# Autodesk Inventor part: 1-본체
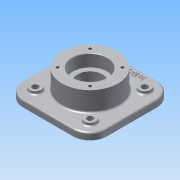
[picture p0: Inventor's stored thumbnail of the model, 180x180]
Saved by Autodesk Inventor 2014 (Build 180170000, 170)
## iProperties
Created: 2015-09
Part Number: 1-본체
Material: 알루미늄 6061
Document SubType Name: Modeling
Designer: study
Density: 2.71 g/cm^3
Appearance: 알루미늄 - 평지
Mass: 1464.66 g
Surface Area: 800.918 cm^2
Volume: 540.466 cm^3
Author: study
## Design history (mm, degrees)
sketch "스케치1"
  geometry: L1 (-45, 75)-(45, 75); L2 (75, 45)-(75, -45); L3 (45, -75)-(-45, -75); L4 (-75, -45)-(-75, 45); L5 (-75, 75)-(75, -75); L6 (75, 75)-(-75, -75); A1 r 30 centre (-45, 45) between (-45, 75) and (-75, 45); A2 r 30 centre (45, 45) between (75, 45) and (45, 75); A3 r 30 centre (45, -45) between (45, -75) and (75, -45); A4 r 30 centre (-45, -45) between (-75, -45) and (-45, -75); 1 further point
  constraints: 12 end point, 8 point on circle, 8 point on line, 8 tangent, 4 centre point, 3 equal radius, 2 midpoint, 2 parallel, 1 horizontal, 1 perpendicular
  dimensions: "d0" = 150 distance of L5.start L6.start; "d1" = 150 distance of L6.start L5.end; "d2" = 30 radius of A1
extrude "돌출1" new body sketch "스케치1" distance "d3" = 12; taper "d4" = 0 deg
node "작업 평면1"
sketch "스케치2"
  geometry: C1 r 50 at (0, 0); 1 further point
  constraints: 1 centre point, 1 coincident
  dimensions: "d6" = 100 diameter of C1
extrude "돌출2" join sketch "스케치2" distance "d7" = 70; taper "d8" = 0 deg
hole "구멍1" diameter "d11" = 45; stored, may be unused: countersink angle "d15" = 90 deg, drill point angle "d17" = 118 deg; dims "d9" = 10, "d10" = 10, "d12" = 6, "d13" = 62, "d14" = 22, "d16" = 8
hole "구멍2" diameter "d20" = 45; stored, may be unused: countersink angle "d24" = 90 deg, drill point angle "d26" = 118 deg; dims "d18" = 10, "d19" = 10, "d21" = 6, "d22" = 62, "d23" = 22, "d25" = 8
sketch "스케치3"
  geometry: C1 r 50 at (0, 0) reference; C2 r 10 at (-49, 49); C3 r 10 at (49, 49); C4 r 10 at (49, -49); C5 r 10 at (-49, -49)
  constraints: 4 centre point, 3 equal radius, 2 horizontal alignment, 2 vertical alignment
  dimensions: "d53" = 98 distance of C3.centre C2.centre; "d54" = 98 distance of C2.centre C5.centre; "d55" = 49 horizontal distance of C1.centre C2.centre; "d56" = 20 diameter of C2; "d57" = 49 horizontal distance of C1.centre C2.centre
sketch "스케치5"
  geometry: L1 (28.991, -28.991)-(-28.991, -28.991); L2 (-28.991, -28.991)-(-28.991, 28.991); L3 (-28.991, 28.991)-(28.991, 28.991); L4 (28.991, 28.991)-(28.991, -28.991); C1 r 50 at (0, 0) reference; 5 further points
  constraints: 8 end point, 5 coincident, 1 horizontal, 9 other
  dimensions: "d37" = 82 distance of L1.start L2.end
hole "구멍4" sketch "스케치5" at (-28.991, 28.991), (28.991, 28.991), (28.991, -28.991), (-28.991, -28.991) diameter "d38" = 4.917; stored, may be unused: countersink angle "d42" = 90 deg, drill point angle "d44" = 118 deg; dims "d39" = 10, "d40" = 62, "d41" = 22, "d43" = 13
node "작업 평면2"
sketch "스케치6"
  geometry: C1 r 50 at (0, 0) reference; 1 further point
  constraints: 1 vertical alignment, 1 other
  dimensions: "d45" = 65 distance of C1.centre point (0, 65)
feature "엠보싱1" sketch "스케치6" dims "d0" = 150, "d1" = 150, "d2" = 30, "d9" = 10, "d10" = 10, "d46" = 1, "d47" = 0
chamfer "모따기1" distance "d48" = 1; stored, may be unused: second distance "d49" = 2, angle "d50" = 45 deg
fillet "모깎기1" dims "d51" = 0.3, "d52" = 3
extrude "돌출4" join sketch "스케치3" distance "d58" = 5; taper "d59" = 0 deg
sketch "스케치7"
  geometry: C1 r 10 at (0, 0) reference; C2 r 10 at (98, 0) reference; C3 r 10 at (98, -98) reference; C4 r 10 at (0, -98) reference; 5 further points
  constraints: 4 coincident
hole "구멍5" sketch "스케치7" at (0, 0), (98, 0), (98, -98), (0, -98) diameter "d60" = 11; stored, may be unused: countersink angle "d64" = 90 deg, drill point angle "d66" = 118 deg; dims "d61" = 6, "d62" = 4, "d63" = 2, "d65" = 8
fillet "모깎기2" dims "d67" = 3
node "솔리드1"
mirror "대칭1"
node "투영된 루프4"
node "투영된 루프5"
node "투영된 루프6"
other parameters: "d5" = 23
